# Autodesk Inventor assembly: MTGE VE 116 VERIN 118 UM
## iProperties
Shininess: 41.0
Angle Display Precision: 2
Document Length Units: 11269
Document Angle Units: 11279
Document Time Units: 11290
Document Mass Units: 11283
Document Length Units Precision: 3
Document Angle Units Precision: 2
Part Number: MTGE VE 116 VERIN 118 UM
Document SubType Name: Assembly
Density: 0.0
Volumn: 0.0
Area: 0.0
PropertySet Name: Model Information
Control State: 0
Master: False
Checked Out: False
